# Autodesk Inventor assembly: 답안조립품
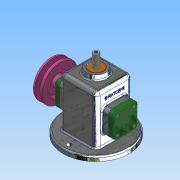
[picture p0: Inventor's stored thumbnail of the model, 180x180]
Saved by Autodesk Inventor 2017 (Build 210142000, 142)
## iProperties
Part Number: 답안조립품
Material: 일반
Document SubType Name: Assembly
Designer: user
Author: user
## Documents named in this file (16)
- C:\Users\user\Desktop\710806V1004\답안조립품.iam
- C:\Users\user\Desktop\710806V1004\본체.ipt
- C:\Users\user\Desktop\710806V1004\V벨트풀리.ipt
- C:\Users\user\Desktop\710806V1004\고정핀 1.2x8.ipt
- C:\Users\user\Desktop\710806V1004\뒤커버.ipt
- C:\Users\user\Desktop\710806V1004\링크.ipt
- C:\Users\user\Desktop\710806V1004\멈춤나사 M3x8.ipt
- C:\Users\user\Desktop\710806V1004\베어링 12x32x10.ipt
- C:\Users\user\Desktop\710806V1004\볼트 M4.ipt
- C:\Users\user\Desktop\710806V1004\부시.ipt
- C:\Users\user\Desktop\710806V1004\슬라이드.ipt
- C:\Users\user\Desktop\710806V1004\앞커버.ipt
- C:\Users\user\Desktop\710806V1004\오일 실 12 25 7.ipt
- C:\Users\user\Desktop\710806V1004\키 4x4x10.ipt
- C:\Users\user\Desktop\710806V1004\편심축.ipt
- C:\Users\user\Desktop\710806V1004\핀 5x18.ipt
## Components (3 placed, 3 different names)
1. V벨트풀리:1 — 각도:2
2. 고정핀 1.2x8:1
3. 핀 5x18:1
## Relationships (1: Angle 1)
- 각도:2 [Angle]: V벨트풀리:1
